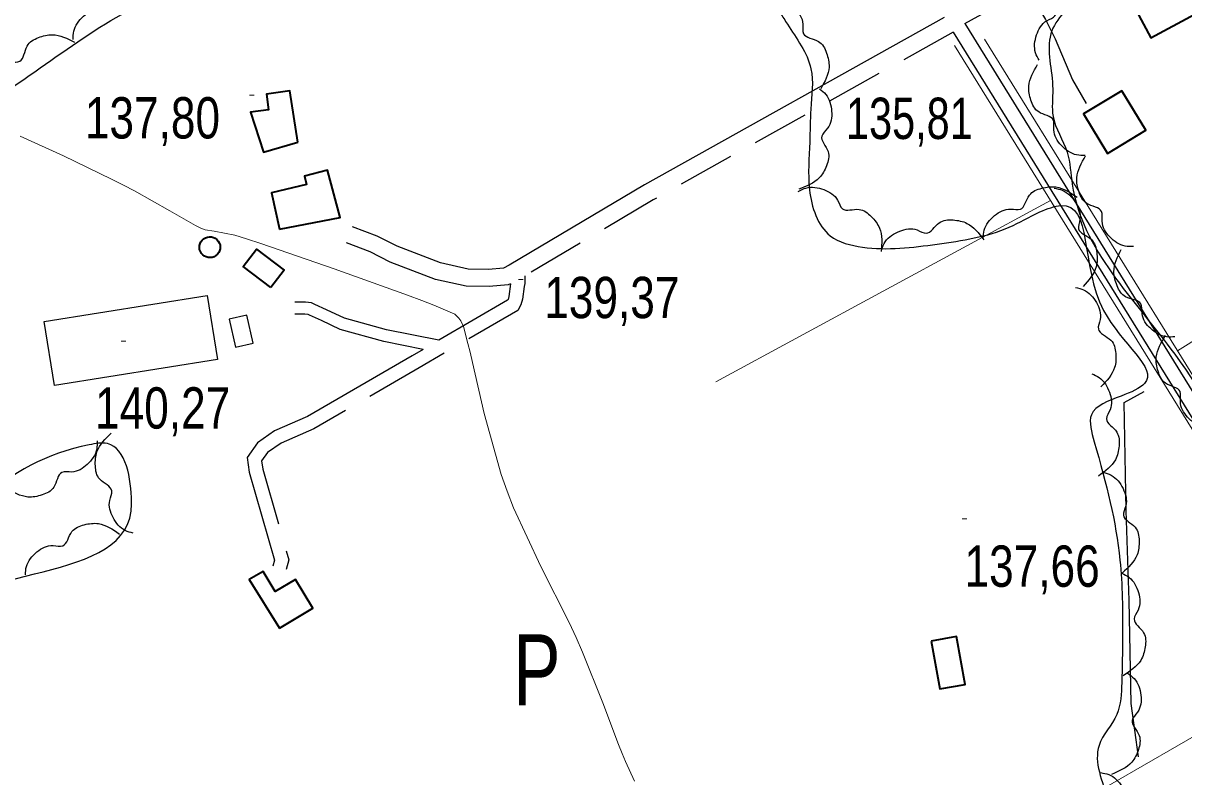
# Model space of a CAD drawing. Extents: x 487425 to 492029, y 4383576 to 4386788.
# Drawn here: x 489600.3 to 489846.1, y 4384556 to 4384715.6 of the extents above; entities that cross this region are included whole.
import ezdxf
from ezdxf.enums import TextEntityAlignment as Align

# ---------------------------------------------------------------- set-up
doc = ezdxf.new("R2010")
doc.units = 0
doc.header["$LTSCALE"] = 4
doc.linetypes.add('LONG_DASHED', pattern=[7.5, 6, -1.5])
doc.linetypes.add('MEDIUM_DASHED', pattern=[4.5, 3, -1.5])
for name, color, linetype, lineweight in [('21', 7, 'Continuous', 25), ('25', 7, 'LONG_DASHED', 25), ('27', 7, 'Continuous', 25), ('38', 7, 'Continuous', 25), ('47', 7, 'Continuous', 35), ('51', 7, 'Continuous', 13), ('58', 7, 'Continuous', 25), ('7', 7, 'Continuous', 13), ('9', 7, 'Continuous', 13)]:
    doc.layers.add(name, color=color, linetype=linetype, lineweight=lineweight)
doc.layers.add('31', color=7, linetype='Continuous')

msp = doc.modelspace()

# ---------------------------------------------------------------- linework, layer by layer
at = {"layer": '21'}
msp.add_lwpolyline([(489643.97, 4384652.87), (489645.31, 4384646.95), (489649.01, 4384647.79), (489647.67, 4384653.71)], close=True, dxfattribs=at)
at = {"layer": '25'}
msp.add_lwpolyline([(489836.53, 4384560.22), (489834.99, 4384571.54), (489834.53, 4384593.29), (489833.92, 4384612.41), (489833.46, 4384635.28), (489837.74, 4384637.59)], dxfattribs=at)
at = {"layer": '27'}
for points in [[(489732.6, 4384813.61), (489705.02, 4384796.52), (489666.92, 4384771.67), (489646.54, 4384760.43), (489641.69, 4384756.43), (489641.33, 4384751.11), (489631.84, 4384747.17), (489625.46, 4384747.24), (489620.65, 4384746.77), (489612.73, 4384742.66), (489603.97, 4384737.8), (489599.25, 4384731.63), (489593.56, 4384725.69), (489583.29, 4384720.18), (489576.95, 4384717.11), (489569.26, 4384713.44), (489548.36, 4384702.8), (489537.94, 4384696.92), (489518.33, 4384687.69), (489517.34, 4384686.65), (489503.16, 4384706.32), (489487.47, 4384725.7), (489482.55, 4384734.31), (489474.81, 4384746.63), (489471.65, 4384752.14), (489472.25, 4384752.43), (489504.83, 4384767.74), (489515.86, 4384773.84), (489523.35, 4384779.46), (489532.64, 4384785.28), (489538.31, 4384789.12), (489541.38, 4384788.86), (489557.26, 4384786.13), (489563.88, 4384788.23), (489594.4, 4384800.41), (489619.8, 4384816.77), (489639.13, 4384827.66), (489650.97, 4384833.37), (489667.41, 4384841.06), (489676.18, 4384846.89), (489686.59, 4384851.57), (489695.63, 4384855.07), (489704.04, 4384855.43), (489707.37, 4384851.86), (489709.57, 4384846.96), (489710.95, 4384843.19), (489711.32, 4384842.59), (489716.74, 4384838.03), (489720.53, 4384834.98), (489723.12, 4384831.73), (489727.39, 4384824.7), (489733.13, 4384814.21)], [(489745.01, 4384434.16), (489741.88, 4384435.77), (489731.89, 4384455.24), (489719.3, 4384475.49), (489713.52, 4384482.38), (489710.45, 4384482.79), (489701.94, 4384479.97), (489694.29, 4384473.75), (489684.93, 4384468.01), (489670.36, 4384460.29), (489658.63, 4384451.65), (489662.1, 4384440.36), (489664.38, 4384436.28), (489663.66, 4384432.01), (489657.1, 4384429.31), (489647.25, 4384427.25), (489637.56, 4384425.86), (489634.19, 4384433.4), (489629.63, 4384441.25), (489626.03, 4384448.12), (489620.16, 4384452.84), (489615.37, 4384454.17), (489608.7, 4384454.54), (489600.63, 4384463.94), (489595.41, 4384473.67), (489593.13, 4384483.53), (489591.31, 4384488.95), (489591.14, 4384493.98), (489592.91, 4384497.11), (489604.12, 4384500.28), (489614.35, 4384502.49), (489616.46, 4384503.22), (489616.77, 4384510.72), (489605.55, 4384527.2), (489582.69, 4384562.42), (489577.28, 4384574.19), (489577, 4384582.37), (489578.24, 4384586.4), (489623.17, 4384612.22), (489623.27, 4384614.25), (489618.16, 4384626.54), (489614.33, 4384626.28), (489590.33, 4384613.72), (489566.41, 4384601.62), (489563.9, 4384605.02), (489549.87, 4384630.99), (489535.22, 4384656.14), (489533.62, 4384660.73), (489577.48, 4384690.62), (489617.75, 4384715.44), (489657.42, 4384734.35), (489696.75, 4384755.65), (489706.97, 4384763.57), (489713.55, 4384768.22), (489724.13, 4384775.37), (489740.28, 4384783.52), (489749.74, 4384784.54), (489750.63, 4384782.95), (489750.29, 4384779.8), (489748, 4384776.53), (489740.83, 4384772.26), (489734.94, 4384769.32), (489733.01, 4384764.39), (489753.67, 4384727.7), (489760.69, 4384717.72), (489762.16, 4384715.37), (489767.16, 4384705.94), (489767.13, 4384697.39), (489766.9, 4384690.41), (489766.86, 4384680.29), (489771.25, 4384670.56), (489778.05, 4384668.15), (489793.89, 4384668.8), (489809.16, 4384672.38), (489815.65, 4384675.6), (489820.09, 4384676.98), (489829.14, 4384654.74), (489837.82, 4384639.27), (489832.84, 4384636.62), (489826.56, 4384632.64), (489827.17, 4384626.93), (489832.59, 4384601.89), (489833.16, 4384585.68), (489832.97, 4384575.93), (489831.92, 4384569.19), (489828.17, 4384562.63), (489830.21, 4384551.13), (489832.31, 4384544.43), (489834.09, 4384535.85), (489834.7, 4384523.54), (489834.59, 4384513.79)], [(490039.24, 4384621.99), (490030.98, 4384615.94), (490027.35, 4384607.18), (490022.74, 4384596.32), (490012.75, 4384587.95), (490007.11, 4384582.95), (489999.21, 4384575.17), (489994.7, 4384572.26), (489981.36, 4384573.28), (489979.73, 4384580.78), (489976.53, 4384586.86), (489964.99, 4384590.72), (489947.56, 4384603.67), (489942.93, 4384609.01), (489944, 4384617.78), (489942.39, 4384629.93), (489935.59, 4384637.52), (489917.08, 4384640.2), (489906.73, 4384640.01), (489893.69, 4384640.95), (489890.63, 4384645.38), (489888.39, 4384649.06), (489888.56, 4384656.26), (489891.74, 4384664.95), (489901.13, 4384673.39), (489917.29, 4384683.99), (489924.04, 4384686.22), (489932.9, 4384691.14), (489936.3, 4384697.06), (489937.36, 4384701.78), (489933.07, 4384720.76), (489925.45, 4384731.28), (489926.67, 4384737.05), (489930.36, 4384742.06), (489931.87, 4384747.08), (489928.59, 4384753.24), (489917.34, 4384750.8), (489906.51, 4384739.58), (489897.43, 4384739.54), (489888.53, 4384745.34), (489884.56, 4384748.35), (489882.84, 4384748.8), (489857.62, 4384739.66), (489844.42, 4384736.7), (489833.07, 4384730.21), (489824.8, 4384721.99), (489817.95, 4384713.31), (489818.37, 4384701.61), (489818.42, 4384695.84), (489821.4, 4384688.25), (489822.5, 4384681.5), (489844.21, 4384645.45), (489870.07, 4384590.56)], [(489815.48, 4384707.71), (489814.72, 4384709.31), (489814.94, 4384713.1), (489817.09, 4384716.1), (489818.84, 4384717.16), (489818.87, 4384720.71), (489820.28, 4384723.34), (489822.69, 4384725.16), (489827.62, 4384725.69)], [(489610.9, 4384712.1), (489611.04, 4384713.87), (489613.12, 4384717.04), (489616.48, 4384718.56), (489618.54, 4384718.59), (489620.33, 4384721.66), (489622.87, 4384723.23), (489625.87, 4384723.61), (489630.41, 4384721.6)], [(489758.7, 4384720.62), (489760.47, 4384720.58), (489763.75, 4384718.68), (489765.45, 4384715.4), (489765.59, 4384713.35), (489768.75, 4384711.72), (489770.45, 4384709.26), (489770.99, 4384706.29), (489769.23, 4384701.66)], [(489592.57, 4384700.42), (489592.56, 4384702.19), (489594.36, 4384705.53), (489597.59, 4384707.32), (489599.63, 4384707.53), (489601.17, 4384710.74), (489603.56, 4384712.52), (489606.52, 4384713.14), (489611.21, 4384711.53)], [(489825.2, 4384687.59), (489823.42, 4384687.68), (489820.2, 4384689.67), (489818.59, 4384693), (489818.49, 4384695.05), (489815.39, 4384696.77), (489813.75, 4384699.26), (489813.29, 4384702.25), (489815.17, 4384706.84)], [(489768.99, 4384701.68), (489770.3, 4384700.49), (489771.54, 4384696.91), (489770.68, 4384693.32), (489769.45, 4384691.68), (489770.78, 4384688.37), (489770.46, 4384685.4), (489768.93, 4384682.81), (489764.56, 4384680.44)], [(489835.46, 4384668.27), (489833.69, 4384668.35), (489830.45, 4384670.32), (489828.82, 4384673.63), (489828.71, 4384675.68), (489825.59, 4384677.38), (489823.93, 4384679.86), (489823.46, 4384682.84), (489825.31, 4384687.45)], [(489764.48, 4384679.96), (489766.11, 4384680.67), (489769.89, 4384680.33), (489772.81, 4384678.07), (489773.81, 4384676.28), (489777.36, 4384676.14), (489779.94, 4384674.63), (489781.68, 4384672.16), (489782.05, 4384667.22)], [(489803.64, 4384669.98), (489803.84, 4384671.74), (489806.05, 4384674.83), (489809.47, 4384676.21), (489811.52, 4384676.17), (489813.44, 4384679.16), (489816.04, 4384680.63), (489819.05, 4384680.89), (489823.51, 4384678.7)], [(489818.67, 4384680.62), (489820.39, 4384680.19), (489823.18, 4384677.62), (489824.12, 4384674.05), (489823.82, 4384672.02), (489826.55, 4384669.74), (489827.68, 4384666.98), (489827.55, 4384663.96), (489824.83, 4384659.81)], [(489782.14, 4384667.7), (489782.89, 4384669.3), (489785.95, 4384671.54), (489789.64, 4384671.78), (489791.57, 4384671.08), (489794.33, 4384673.32), (489797.26, 4384673.9), (489800.2, 4384673.19), (489803.74, 4384669.72)], [(489844.25, 4384649.17), (489842.48, 4384649.14), (489839.11, 4384650.89), (489837.27, 4384654.09), (489837.03, 4384656.13), (489833.8, 4384657.61), (489831.99, 4384659.98), (489831.32, 4384662.93), (489832.86, 4384667.65)], [(489823.19, 4384659.6), (489824.9, 4384659.11), (489827.6, 4384656.43), (489828.41, 4384652.83), (489828.02, 4384650.81), (489830.67, 4384648.44), (489831.7, 4384645.64), (489831.46, 4384642.63), (489828.58, 4384638.58)], [(489851.88, 4384629.96), (489850.11, 4384630.08), (489846.93, 4384632.15), (489845.39, 4384635.5), (489845.34, 4384637.55), (489842.26, 4384639.33), (489840.68, 4384641.86), (489840.28, 4384644.86), (489842.26, 4384649.41)], [(489826.62, 4384641.33), (489828.21, 4384640.53), (489830.36, 4384637.41), (489830.5, 4384633.72), (489829.75, 4384631.81), (489831.91, 4384628.98), (489832.41, 4384626.04), (489831.62, 4384623.12), (489828.05, 4384619.68)], [(489623.64, 4384607.58), (489621.95, 4384608.13), (489619.36, 4384610.9), (489618.67, 4384614.52), (489619.12, 4384616.53), (489616.55, 4384618.99), (489615.62, 4384621.83), (489615.96, 4384624.83), (489618.97, 4384628.77)], [(489615.99, 4384627.15), (489615.9, 4384625.37), (489613.91, 4384622.14), (489610.59, 4384620.53), (489608.54, 4384620.44), (489606.83, 4384617.32), (489604.33, 4384615.68), (489601.35, 4384615.23), (489596.75, 4384617.1)], [(489829.06, 4384620.45), (489830.74, 4384619.85), (489833.25, 4384617.01), (489833.83, 4384613.36), (489833.32, 4384611.37), (489835.81, 4384608.83), (489836.66, 4384605.97), (489836.23, 4384602.98), (489833.1, 4384599.13)], [(489600.81, 4384598.76), (489601.02, 4384600.52), (489603.24, 4384603.6), (489606.67, 4384604.97), (489608.72, 4384604.91), (489610.65, 4384607.9), (489613.26, 4384609.36), (489616.27, 4384609.6), (489620.72, 4384607.39)], [(489832.99, 4384599.09), (489834.54, 4384598.21), (489836.52, 4384594.98), (489836.45, 4384591.28), (489835.6, 4384589.41), (489837.61, 4384586.48), (489837.95, 4384583.51), (489837, 4384580.64), (489833.25, 4384577.39)], [(489834.23, 4384577.93), (489835.6, 4384576.8), (489837.01, 4384573.28), (489836.33, 4384569.66), (489835.18, 4384567.94), (489836.66, 4384564.72), (489836.5, 4384561.74), (489835.08, 4384559.07), (489830.84, 4384556.5)], [(489828.51, 4384556.86), (489830.24, 4384556.45), (489833.05, 4384553.9), (489834.02, 4384550.33), (489833.73, 4384548.3), (489836.48, 4384546.05), (489837.63, 4384543.29), (489837.53, 4384540.27), (489834.84, 4384536.1)]]:
    msp.add_spline(points, degree=3, dxfattribs=at)
at = {"layer": '38'}
for p, q in [((489799.74, 4384715.5), (489851.51, 4384631.86)), ((489797.27, 4384713.7), (489848.93, 4384630.26))]:
    msp.add_line(p, q, dxfattribs=at)
at = {"layer": '38', "linetype": 'MEDIUM_DASHED'}
for points in [[(489799.74, 4384715.5), (489823.09, 4384728.41), (489858.93, 4384749.33), (489875.06, 4384759.76)], [(489797.27, 4384713.7), (489733.75, 4384678.17), (489706.55, 4384662.06)], [(489703.56, 4384660.4), (489703.05, 4384660.15), (489699.01, 4384659.79), (489694.11, 4384659.85), (489687.62, 4384661.32), (489678.08, 4384665), (489673.83, 4384667.15), (489668.81, 4384669.06)], [(489706.55, 4384662.06), (489706.54, 4384660.44), (489706.44, 4384659.79), (489706.1, 4384657.12), (489705.75, 4384655.92), (489705.07, 4384654.75), (489684.16, 4384642.57), (489661.86, 4384629.64), (489654.99, 4384626.67), (489652.04, 4384624.63), (489650.83, 4384622.86), (489651.06, 4384621.11), (489656.57, 4384601.93), (489656.06, 4384599.85)], [(489685.05, 4384646.49), (489676.68, 4384648.16), (489667.49, 4384650.7), (489663.53, 4384652.58), (489660.97, 4384653.75), (489660.7, 4384653.89), (489660, 4384653.95), (489657.85, 4384653.98)]]:
    msp.add_lwpolyline(points, dxfattribs=at)
at = {"layer": '38'}
for points in [[(489809.35, 4384721.13), (489814.75, 4384719.84), (489816.84, 4384716.39), (489818.85, 4384712.26), (489822.57, 4384703.55), (489825.41, 4384698.59)], [(489795.35, 4384716.8), (489731.93, 4384681.33), (489703.26, 4384664.34), (489702.03, 4384663.71), (489698.88, 4384663.44), (489694.54, 4384663.49), (489688.69, 4384664.82), (489679.56, 4384668.34), (489675.31, 4384670.49), (489670.1, 4384672.46)], [(489703.56, 4384660.4), (489703.21, 4384657.72), (489703.03, 4384657.08), (489702.92, 4384656.9), (489688.34, 4384648.42)], [(489688.34, 4384648.42), (489677.26, 4384650.62), (489668.38, 4384653.09), (489664.6, 4384654.88), (489662.07, 4384656.03), (489661.41, 4384656.37), (489660.12, 4384656.48), (489657.89, 4384656.51)], [(489685.05, 4384646.49), (489682.68, 4384645.11), (489660.53, 4384632.27), (489653.55, 4384629.25), (489649.92, 4384626.73), (489647.77, 4384623.59), (489648.17, 4384620.51), (489653.53, 4384601.87), (489653.2, 4384600.56)]]:
    msp.add_lwpolyline(points, dxfattribs=at)
at = {"layer": '47'}
for points in [[(489834.47, 4384721.21), (489839.14, 4384712.49), (489848.48, 4384717.49), (489843.81, 4384726.21)], [(489658.5, 4384690.37), (489656.82, 4384701.27), (489651.83, 4384700.54), (489652.31, 4384697.22), (489648.47, 4384696.72), (489651.2, 4384688.28)], [(489832.99, 4384701.27), (489824.88, 4384696.35), (489829.95, 4384688), (489838.06, 4384692.92)], [(489654.61, 4384671.96), (489667.47, 4384674.44), (489664.78, 4384684.46), (489659.9, 4384683.15), (489660.35, 4384681.44), (489652.9, 4384679.63)], [(489652.75, 4384659.6), (489646.94, 4384664.06), (489649.76, 4384667.74), (489655.57, 4384663.28)], [(489654.63, 4384587.48), (489661.65, 4384591.68), (489657.99, 4384597.77), (489653.7, 4384595.2), (489651.12, 4384599.48), (489648.21, 4384597.74)], [(489792.63, 4384584.71), (489794.47, 4384574.58), (489799.81, 4384575.55), (489797.97, 4384585.68)]]:
    msp.add_lwpolyline(points, close=True, dxfattribs=at)
msp.add_ellipse((489639.86, 4384668.14), major_axis=(2.01, 0.92), ratio=0.999971, dxfattribs=at)
at = {"layer": '51'}
for p, q in [((489853.04, 4384632.81), (489803.9, 4384712.22)), ((489847.88, 4384629.61), (489797.58, 4384710.87)), ((489817.91, 4384678.05), (489747.02, 4384639.59)), ((489713.73, 4384487.03), (489876.69, 4384580.98))]:
    msp.add_line(p, q, dxfattribs=at)
msp.add_lwpolyline([(489844.77, 4384646.18), (489937.07, 4384704.03), (490044.79, 4384770.51), (490164.9, 4384843.7), (490232.51, 4384888.56)], dxfattribs=at)
at = {"layer": '58'}
msp.add_lwpolyline([(489641.47, 4384644.35), (489606.95, 4384638.87), (489604.8, 4384652.42), (489639.32, 4384657.9)], close=True, dxfattribs=at)
at = {"layer": '7'}
for p, q in [((489648.28, 4384700.31), (489649.28, 4384700.31)), ((489705.23, 4384661.32), (489706.23, 4384661.32)), ((489621.06, 4384648.25), (489622.06, 4384648.25)), ((489799.18, 4384610.59), (489800.18, 4384610.59))]:
    msp.add_line(p, q, dxfattribs=at)
at = {"layer": '9'}
msp.add_lwpolyline([(489599.72, 4384691.64), (489608.86, 4384687.47), (489619.05, 4384682.56), (489621.56, 4384681.29), (489623.94, 4384680.04), (489631.39, 4384675.83), (489636.82, 4384672.73), (489637.93, 4384672.19), (489638.86, 4384671.79), (489640.78, 4384671.5), (489645.15, 4384670.65), (489647.63, 4384669.91), (489650.66, 4384668.93), (489666.18, 4384663.57), (489681.73, 4384657.95), (489684.77, 4384656.82), (489687.28, 4384655.87), (489691.77, 4384653.95), (489692.61, 4384653.11), (489692.82, 4384652.83), (489693, 4384652.54), (489693.57, 4384651.36), (489694.52, 4384647.75), (489694.96, 4384645.93), (489695.47, 4384643.75), (489697.93, 4384632.95), (489701.57, 4384620), (489702.83, 4384616.47), (489704.19, 4384612.97), (489709.99, 4384600.53), (489715.96, 4384588.64), (489717.42, 4384585.48), (489718.81, 4384582.37), (489723.11, 4384571.65), (489726.42, 4384562.81), (489727.18, 4384560.9), (489727.86, 4384559.22), (489729.76, 4384555.09)], dxfattribs=at)

# ---------------------------------------------------------------- texts
at = {"layer": '31', "width": 0.75}
msp.add_text('P', height=15, dxfattribs=at).set_placement((489709.11, 4384571.14), align=Align.CENTER)
at = {"layer": '7'}
for s, width, p in [('137,80', 0.8, (489613.39, 4384691.16)), ('135,81', 0.75, (489774.58, 4384691.05)), ('139,37', 0.8, (489710.68, 4384653.11)), ('140,27', 0.8, (489615.55, 4384629.72)), ('137,66', 0.8, (489799.68, 4384596.22))]:
    msp.add_text(s, height=8.75, dxfattribs=dict(at, width=width)).set_placement(p)

doc.saveas('drawing.dxf')
